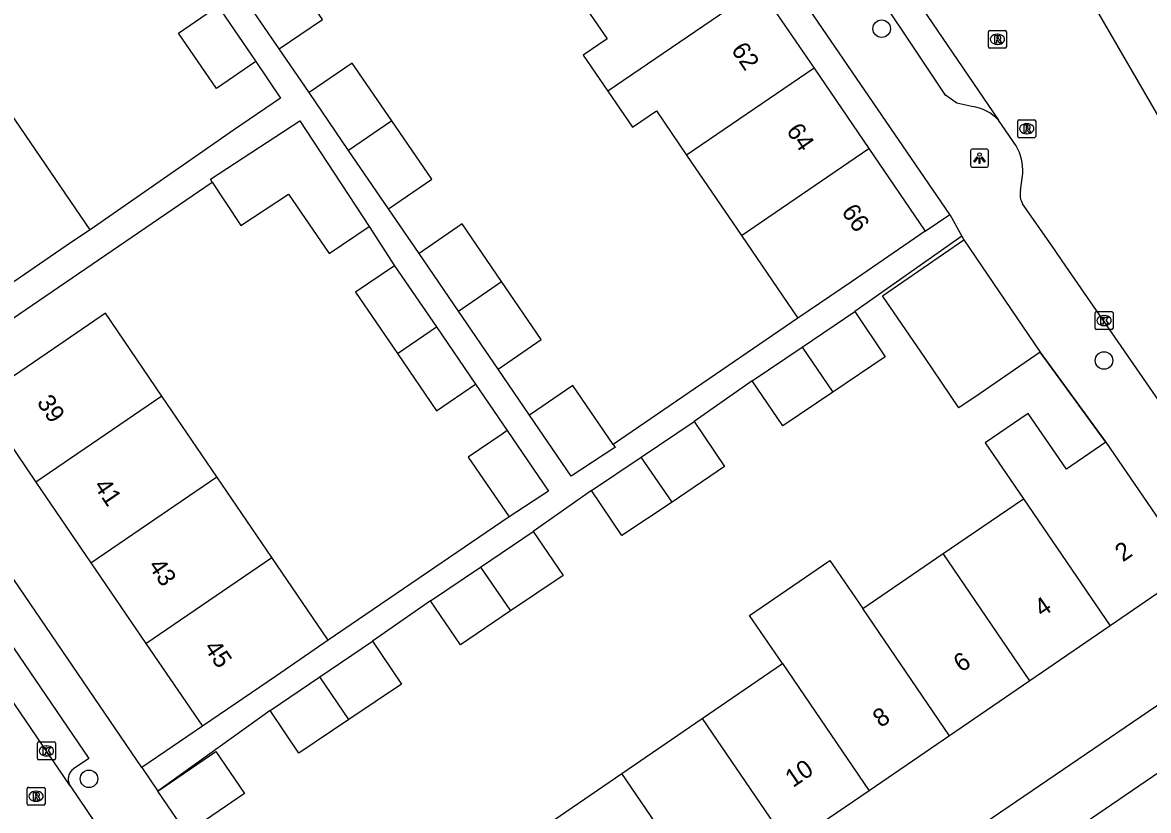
# Model space of a CAD drawing. Extents: x 157466 to 158888, y 383063 to 384677.
# Drawn here: x 158262.6 to 158325.5, y 383778.8 to 383822.7 of the extents above; entities that cross this region are included whole.
import ezdxf

# ---------------------------------------------------------------- set-up
doc = ezdxf.new("R2010")
doc.units = 0
for name, color, linetype in [('IMGEO_Boom', 7, 'Continuous'), ('IMGEO_Kolk', 7, 'Continuous'), ('IMGEO_Lichtpunt', 7, 'Continuous'), ('IMGEO_Muur', 7, 'Continuous'), ('IMGEO_Pand', 7, 'Continuous'), ('IMGEO_Pand_nummerreeks', 7, 'Continuous'), ('IMGEO_Rijbaan_lokaal_open', 7, 'Continuous'), ('IMGEO_Rioolput', 7, 'Continuous'), ('IMGEO_Voetpad_open', 7, 'Continuous')]:
    doc.layers.add(name, color=color, linetype=linetype)

msp = doc.modelspace()

# ---------------------------------------------------------------- linework, layer by layer
at = {"layer": 'IMGEO_Boom'}
for centre in [(158310.608, 383822.389), (158323.018, 383803.876), (158266.36, 383780.534)]:
    msp.add_circle(centre, 0.489, dxfattribs=at)
at = {"layer": 'IMGEO_Kolk'}
for p, q in [((158322.523, 383805.675), (158322.523, 383806.527)), ((158322.598, 383806.601), (158323.45, 383806.601)), ((158323.011, 383806.381), (158323.036, 383806.381)), ((158323.524, 383806.527), (158323.524, 383805.675)), ((158323.45, 383805.601), (158322.598, 383805.601)), ((158323.034, 383805.821), (158323.009, 383805.821)), ((158263.48, 383781.662), (158263.48, 383782.514)), ((158263.555, 383782.588), (158264.407, 383782.588)), ((158263.968, 383782.368), (158263.993, 383782.368)), ((158264.481, 383782.514), (158264.481, 383781.662)), ((158263.991, 383781.808), (158263.966, 383781.808)), ((158264.407, 383781.588), (158263.555, 383781.588))]:
    msp.add_line(p, q, dxfattribs=at)
for points in [[(158322.523, 383805.675), (158322.523, 383806.527)], [(158322.598, 383806.601), (158323.45, 383806.601)], [(158322.844, 383806.301), (158322.967, 383806.301), (158322.967, 383806.15), (158323.097, 383806.301), (158323.261, 383806.301), (158323.115, 383806.15), (158323.268, 383805.901), (158323.116, 383805.901), (158323.031, 383806.065), (158322.967, 383805.998), (158322.967, 383805.901), (158322.844, 383805.901), (158322.844, 383806.301)], [(158323.524, 383806.527), (158323.524, 383805.675)], [(158323.45, 383805.601), (158322.598, 383805.601)], [(158263.48, 383781.662), (158263.48, 383782.514)], [(158263.555, 383782.588), (158264.407, 383782.588)], [(158263.801, 383782.288), (158263.924, 383782.288), (158263.924, 383782.137), (158264.054, 383782.288), (158264.218, 383782.288), (158264.072, 383782.137), (158264.225, 383781.888), (158264.073, 383781.888), (158263.988, 383782.052), (158263.924, 383781.985), (158263.924, 383781.888), (158263.801, 383781.888), (158263.801, 383782.288)], [(158264.481, 383782.514), (158264.481, 383781.662)], [(158264.407, 383781.588), (158263.555, 383781.588)]]:
    msp.add_lwpolyline(points, dxfattribs=at)
for centre, start, end in [((158322.6, 383806.525), 91.55205, 178.44795), ((158322.6, 383806.525), 91.55205, 178.44795), ((158323.448, 383806.525), 1.55205, 88.44795), ((158323.448, 383806.525), 1.55205, 88.44795), ((158322.6, 383805.677), 181.55205, 268.44795), ((158322.6, 383805.677), 181.55205, 268.44795), ((158323.448, 383805.677), 271.55205, 358.44795), ((158323.448, 383805.677), 271.55205, 358.44795), ((158263.557, 383782.512), 91.55205, 178.44795), ((158263.557, 383782.512), 91.55205, 178.44795), ((158264.405, 383782.512), 1.55205, 88.44795), ((158264.405, 383782.512), 1.55205, 88.44795), ((158263.557, 383781.664), 181.55205, 268.44795), ((158263.557, 383781.664), 181.55205, 268.44795), ((158264.405, 383781.664), 271.55205, 358.44795), ((158264.405, 383781.664), 271.55205, 358.44795)]:
    msp.add_arc(centre, 0.0765, start, end, dxfattribs=at)
for centre, major_axis, ratio, start_param, end_param in [((158323.01, 383806.101), (-0.387, 0.002), 0.722429, 4.712389, 7.853982), ((158323.035, 383806.101), (-0.39, 0.002), 0.717154, 1.570796, 4.712389), ((158263.967, 383782.088), (-0.387, 0.002), 0.722429, 4.712389, 7.853982), ((158263.992, 383782.088), (-0.39, 0.002), 0.717154, 1.570796, 4.712389)]:
    msp.add_ellipse(centre, major_axis=major_axis, ratio=ratio, start_param=start_param, end_param=end_param, dxfattribs=at)
at = {"layer": 'IMGEO_Lichtpunt'}
for p, q in [((158315.572, 383815.572), (158315.572, 383814.765)), ((158315.572, 383815.572), (158315.572, 383814.765)), ((158316.474, 383815.667), (158315.666, 383815.667)), ((158316.474, 383815.667), (158315.666, 383815.667)), ((158316.568, 383814.765), (158316.568, 383815.572)), ((158316.568, 383814.765), (158316.568, 383815.572)), ((158315.666, 383814.671), (158316.474, 383814.671)), ((158315.666, 383814.671), (158316.474, 383814.671))]:
    msp.add_line(p, q, dxfattribs=at)
for points in [[(158315.946, 383815.236), (158315.985, 383815.208), (158315.797, 383814.946), (158315.759, 383814.973), (158315.946, 383815.236)], [(158316.048, 383815.188), (158316.095, 383815.188), (158316.095, 383814.866), (158316.048, 383814.866), (158316.048, 383815.188)], [(158316.158, 383815.208), (158316.196, 383815.235), (158316.383, 383814.973), (158316.344, 383814.945), (158316.158, 383815.208)]]:
    msp.add_lwpolyline(points, dxfattribs=at)
msp.add_circle((158316.071, 383815.37), 0.0994, dxfattribs=at)
for centre, start, end in [((158315.666, 383815.572), 90, 180), ((158315.666, 383815.572), 90, 180), ((158316.474, 383815.572), 0, 90), ((158316.474, 383815.572), 0, 90), ((158315.666, 383814.765), 180, 270), ((158315.666, 383814.765), 180, 270), ((158316.474, 383814.765), 270, 0), ((158316.474, 383814.765), 270, 360)]:
    msp.add_arc(centre, 0.0946, start, end, dxfattribs=at)
at = {"layer": 'IMGEO_Muur'}
msp.add_lwpolyline([(158323.13, 383799.314), (158319.462, 383804.339)], dxfattribs=at)
at = {"layer": 'IMGEO_Pand'}
for points in [[(158276.975, 383821.258), (158279.388, 383822.904), (158277.126, 383826.21)], [(158276.975, 383821.258), (158274.713, 383824.564)], [(158303.777, 383824.672), (158295.318, 383818.898)], [(158303.777, 383824.672), (158306.839, 383820.185)], [(158293.599, 383824.3), (158295.291, 383821.821), (158293.948, 383820.905), (158295.318, 383818.898)], [(158275.661, 383820.551), (158273.47, 383819.055), (158271.361, 383822.144), (158273.552, 383823.637)], [(158273.552, 383823.637), (158273.728, 383823.38), (158275.661, 383820.551)], [(158283.261, 383817.243), (158281.055, 383820.468), (158278.641, 383818.821)], [(158306.839, 383820.185), (158299.721, 383815.328)], [(158306.839, 383820.185), (158309.9, 383815.699)], [(158280.847, 383815.596), (158278.641, 383818.821)], [(158295.318, 383818.898), (158296.69, 383816.887), (158298.032, 383817.803), (158299.721, 383815.328)], [(158266.421, 383811.174), (158261.716, 383818.073)], [(158273.238, 383813.832), (158273.136, 383813.988), (158278.13, 383817.257), (158281.992, 383811.358)], [(158283.261, 383817.243), (158280.847, 383815.596)], [(158283.075, 383812.338), (158285.489, 383813.986), (158283.261, 383817.243)], [(158283.075, 383812.338), (158280.847, 383815.596)], [(158302.783, 383810.842), (158309.9, 383815.699)], [(158309.9, 383815.699), (158313.044, 383811.091)], [(158299.721, 383815.328), (158302.783, 383810.842)], [(158273.238, 383813.832), (158274.827, 383811.404), (158277.501, 383813.155), (158279.766, 383809.84), (158281.992, 383811.358)], [(158266.421, 383811.174), (158265.388, 383810.47), (158261.257, 383807.652)], [(158289.392, 383808.28), (158287.194, 383811.494), (158284.78, 383809.846)], [(158302.783, 383810.842), (158305.927, 383806.234)], [(158313.044, 383811.091), (158308.915, 383808.273), (158305.927, 383806.234)], [(158319.462, 383804.339), (158316.102, 383802.042), (158314.923, 383801.236), (158313.008, 383804.037), (158310.648, 383807.489), (158315.198, 383810.6)], [(158315.198, 383810.6), (158319.462, 383804.339)], [(158286.977, 383806.632), (158284.78, 383809.846)], [(158283.42, 383809.165), (158281.243, 383807.679), (158283.578, 383804.261)], [(158283.42, 383809.165), (158285.755, 383805.746)], [(158286.977, 383806.632), (158289.392, 383808.28)], [(158289.189, 383803.398), (158291.605, 383805.047), (158289.392, 383808.28)], [(158270.426, 383801.884), (158267.272, 383806.508), (158264.371, 383804.53), (158260.24, 383801.712), (158263.394, 383797.087)], [(158289.189, 383803.398), (158286.977, 383806.632)], [(158306.16, 383804.618), (158309.102, 383806.604)], [(158309.102, 383806.604), (158310.801, 383804.085), (158307.874, 383802.11)], [(158283.578, 383804.261), (158285.755, 383805.746)], [(158285.755, 383805.746), (158287.94, 383802.549)], [(158283.578, 383804.261), (158285.762, 383801.064), (158287.94, 383802.549)], [(158303.383, 383802.745), (158306.16, 383804.618)], [(158306.16, 383804.618), (158307.874, 383802.11)], [(158295.609, 383799.193), (158293.366, 383802.472), (158290.95, 383800.823)], [(158307.874, 383802.11), (158305.082, 383800.227), (158303.383, 383802.745)], [(158270.426, 383801.884), (158263.394, 383797.087)], [(158273.494, 383797.384), (158270.426, 383801.884)], [(158295.609, 383799.193), (158295.723, 383799.027), (158295.659, 383798.983), (158293.277, 383797.422), (158290.95, 383800.823)], [(158323.13, 383799.314), (158320.925, 383797.806), (158318.794, 383800.924), (158316.388, 383799.28), (158318.52, 383796.162)], [(158289.706, 383799.964), (158289.419, 383799.768), (158287.528, 383798.479), (158289.804, 383795.148)], [(158289.706, 383799.964), (158292.009, 383796.592), (158289.804, 383795.148)], [(158297.189, 383798.485), (158300.131, 383800.471)], [(158300.131, 383800.471), (158301.83, 383797.952), (158298.903, 383795.977)], [(158323.13, 383799.314), (158327.979, 383792.222)], [(158294.416, 383796.615), (158297.189, 383798.485)], [(158298.903, 383795.977), (158297.189, 383798.485)], [(158266.462, 383792.588), (158273.494, 383797.384)], [(158276.563, 383792.885), (158273.494, 383797.384)], [(158263.394, 383797.087), (158266.462, 383792.588)], [(158298.903, 383795.977), (158296.11, 383794.103), (158294.416, 383796.615)], [(158314.035, 383793.096), (158318.52, 383796.162)], [(158318.52, 383796.162), (158323.368, 383789.07)], [(158288.217, 383792.351), (158291.161, 383794.338)], [(158291.161, 383794.338), (158292.818, 383791.882), (158289.888, 383789.906)], [(158309.549, 383790.029), (158314.035, 383793.096)], [(158318.883, 383786.003), (158314.035, 383793.096)], [(158266.462, 383792.588), (158269.531, 383788.089)], [(158269.531, 383788.089), (158276.563, 383792.885)], [(158279.716, 383788.261), (158276.563, 383792.885)], [(158285.43, 383790.471), (158288.217, 383792.351)], [(158288.217, 383792.351), (158289.888, 383789.906)], [(158305.064, 383786.963), (158303.228, 383789.648), (158307.713, 383792.714), (158309.549, 383790.029)], [(158327.979, 383792.222), (158323.368, 383789.07)], [(158289.888, 383789.906), (158287.087, 383788.017), (158285.43, 383790.471)], [(158314.397, 383782.937), (158309.549, 383790.029)], [(158323.368, 383789.07), (158318.883, 383786.003)], [(158269.531, 383788.089), (158272.684, 383783.465)], [(158279.716, 383788.261), (158276.815, 383786.283), (158272.684, 383783.465)], [(158279.247, 383786.219), (158282.191, 383788.206)], [(158282.191, 383788.206), (158283.81, 383785.806), (158280.867, 383783.848)], [(158300.579, 383783.896), (158305.064, 383786.963)], [(158305.064, 383786.963), (158309.912, 383779.87)], [(158276.472, 383784.347), (158279.247, 383786.219)], [(158280.867, 383783.848), (158279.247, 383786.219)], [(158318.883, 383786.003), (158314.397, 383782.937)], [(158280.867, 383783.848), (158278.078, 383781.967), (158276.472, 383784.347)], [(158296.094, 383780.83), (158300.579, 383783.896)], [(158300.579, 383783.896), (158305.428, 383776.804)], [(158314.397, 383782.937), (158309.912, 383779.87)], [(158270.2, 383779.842), (158273.433, 383782.053), (158275.031, 383779.716), (158271.798, 383777.505)], [(158291.609, 383777.764), (158296.094, 383780.83)], [(158300.943, 383773.738), (158296.094, 383780.83)], [(158271.798, 383777.505), (158270.2, 383779.842)], [(158309.912, 383779.87), (158305.428, 383776.804)]]:
    msp.add_lwpolyline(points, dxfattribs=at)
at = {"layer": 'IMGEO_Rijbaan_lokaal_open'}
for points in [[(158266.381, 383891.427), (158290.926, 383855.558), (158294.957, 383849.841), (158317.136, 383817.278)], [(158320.491, 383827.07), (158327.485, 383815.039)], [(158318.12, 383815.849), (158317.136, 383817.278)], [(158318.359, 383813.367), (158318.48, 383814.317)], [(158331.81, 383793.339), (158322.603, 383806.659), (158320.882, 383809.145), (158320.086, 383810.314), (158318.47, 383812.617)], [(158265.297, 383780.146), (158255.069, 383795.151)], [(158265.297, 383780.146), (158265.304, 383780.135), (158267.164, 383777.394)]]:
    msp.add_lwpolyline(points, dxfattribs=at)
for centre, radius, start, end in [((158315.763, 383814.487), 2.723, 356.42583, 30.02185), ((158319.321, 383813.126), 0.992, 165.94685, 210.89047)]:
    msp.add_arc(centre, radius, start, end, dxfattribs=at)
at = {"layer": 'IMGEO_Rioolput'}
for p, q in [((158316.568, 383821.37), (158316.568, 383822.222)), ((158316.643, 383822.296), (158317.495, 383822.296)), ((158317.056, 383822.076), (158317.081, 383822.076)), ((158317.569, 383822.222), (158317.569, 383821.37)), ((158317.495, 383821.296), (158316.643, 383821.296)), ((158317.079, 383821.516), (158317.054, 383821.516)), ((158318.206, 383816.381), (158318.206, 383817.233)), ((158318.281, 383817.307), (158319.133, 383817.307)), ((158318.694, 383817.087), (158318.719, 383817.087)), ((158319.207, 383817.233), (158319.207, 383816.381)), ((158319.133, 383816.307), (158318.281, 383816.307)), ((158318.717, 383816.527), (158318.692, 383816.527)), ((158262.9, 383779.131), (158262.9, 383779.983)), ((158262.975, 383780.057), (158263.827, 383780.057)), ((158263.388, 383779.837), (158263.413, 383779.837)), ((158263.901, 383779.983), (158263.901, 383779.131)), ((158263.411, 383779.277), (158263.386, 383779.277)), ((158263.827, 383779.057), (158262.975, 383779.057))]:
    msp.add_line(p, q, dxfattribs=at)
for points in [[(158316.568, 383821.37), (158316.568, 383822.222)], [(158316.643, 383822.296), (158317.495, 383822.296)], [(158317.157, 383821.994), (158316.905, 383821.996), (158316.905, 383821.596)], [(158317.083, 383821.915), (158317.029, 383821.915), (158317.029, 383821.834)], [(158317.569, 383822.222), (158317.569, 383821.37)], [(158317.495, 383821.296), (158316.643, 383821.296)], [(158316.905, 383821.596), (158317.029, 383821.596), (158317.029, 383821.758), (158317.04, 383821.758)], [(158317.029, 383821.834), (158317.081, 383821.834)], [(158317.087, 383821.729), (158317.158, 383821.596), (158317.298, 383821.596), (158317.233, 383821.722)], [(158318.206, 383816.381), (158318.206, 383817.233)], [(158318.281, 383817.307), (158319.133, 383817.307)], [(158318.795, 383817.005), (158318.543, 383817.007), (158318.543, 383816.607)], [(158318.721, 383816.926), (158318.667, 383816.926), (158318.667, 383816.845)], [(158318.667, 383816.845), (158318.719, 383816.845)], [(158319.207, 383817.233), (158319.207, 383816.381)], [(158319.133, 383816.307), (158318.281, 383816.307)], [(158318.543, 383816.607), (158318.667, 383816.607), (158318.667, 383816.769), (158318.678, 383816.769)], [(158318.725, 383816.74), (158318.796, 383816.607), (158318.936, 383816.607), (158318.871, 383816.733)], [(158262.9, 383779.131), (158262.9, 383779.983)], [(158262.975, 383780.057), (158263.827, 383780.057)], [(158263.489, 383779.755), (158263.237, 383779.757), (158263.237, 383779.357)], [(158263.901, 383779.983), (158263.901, 383779.131)], [(158263.237, 383779.357), (158263.361, 383779.357), (158263.361, 383779.519), (158263.372, 383779.519)], [(158263.415, 383779.676), (158263.361, 383779.676), (158263.361, 383779.595)], [(158263.361, 383779.595), (158263.413, 383779.595)], [(158263.419, 383779.49), (158263.49, 383779.357), (158263.63, 383779.357), (158263.565, 383779.483)], [(158263.827, 383779.057), (158262.975, 383779.057)]]:
    msp.add_lwpolyline(points, dxfattribs=at)
for centre, radius, start, end in [((158316.645, 383822.22), 0.0765, 91.55205, 178.44795), ((158316.645, 383822.22), 0.0765, 91.55205, 178.44795), ((158317.089, 383821.819), 0.0964, 77.00612, 93.18647), ((158317.103, 383821.876), 0.0378, 276.66336, 79.67722), ((158317.156, 383821.884), 0.109, 350.36119, 89.41601), ((158317.154, 383821.884), 0.112, 277.58423, 350.98172), ((158317.493, 383822.22), 0.0765, 1.55205, 88.44795), ((158317.493, 383822.22), 0.0765, 1.55205, 88.44795), ((158316.645, 383821.372), 0.0765, 181.55205, 268.44795), ((158316.645, 383821.372), 0.0765, 181.55205, 268.44795), ((158317.039, 383821.705), 0.0533, 26.02933, 88.69889), ((158317.065, 383822.023), 0.19, 274.7715, 282.96867), ((158317.138, 383821.669), 0.108, 29.51342, 73.79051), ((158317.493, 383821.372), 0.0765, 271.55205, 358.44795), ((158317.493, 383821.372), 0.0765, 271.55205, 358.44795), ((158318.283, 383817.231), 0.0765, 91.55205, 178.44795), ((158318.283, 383817.231), 0.0765, 91.55205, 178.44795), ((158318.703, 383817.034), 0.19, 274.7715, 282.96867), ((158318.727, 383816.83), 0.0964, 77.00612, 93.18647), ((158318.741, 383816.887), 0.0378, 276.66336, 79.67722), ((158318.794, 383816.895), 0.109, 350.36119, 89.41601), ((158318.792, 383816.895), 0.112, 277.58423, 350.98172), ((158319.131, 383817.231), 0.0765, 1.55205, 88.44795), ((158319.131, 383817.231), 0.0765, 1.55205, 88.44795), ((158318.283, 383816.383), 0.0765, 181.55205, 268.44795), ((158318.283, 383816.383), 0.0765, 181.55205, 268.44795), ((158318.677, 383816.716), 0.0533, 26.02933, 88.69889), ((158318.776, 383816.68), 0.108, 29.51342, 73.79051), ((158319.131, 383816.383), 0.0765, 271.55205, 358.44795), ((158319.131, 383816.383), 0.0765, 271.55205, 358.44795), ((158262.977, 383779.981), 0.0765, 91.55205, 178.44795), ((158262.977, 383779.981), 0.0765, 91.55205, 178.44795), ((158263.488, 383779.645), 0.109, 350.36119, 89.41601), ((158263.825, 383779.981), 0.0765, 1.55205, 88.44795), ((158263.825, 383779.981), 0.0765, 1.55205, 88.44795), ((158262.977, 383779.133), 0.0765, 181.55205, 268.44795), ((158262.977, 383779.133), 0.0765, 181.55205, 268.44795), ((158263.371, 383779.466), 0.0533, 26.02933, 88.69889), ((158263.397, 383779.784), 0.19, 274.7715, 282.96867), ((158263.421, 383779.58), 0.0964, 77.00612, 93.18647), ((158263.435, 383779.637), 0.0378, 276.66336, 79.67722), ((158263.486, 383779.645), 0.112, 277.58423, 350.98172), ((158263.47, 383779.43), 0.108, 29.51342, 73.79051), ((158263.825, 383779.133), 0.0765, 271.55205, 358.44795), ((158263.825, 383779.133), 0.0765, 271.55205, 358.44795)]:
    msp.add_arc(centre, radius, start, end, dxfattribs=at)
for centre, major_axis, ratio, start_param, end_param in [((158317.055, 383821.796), (-0.387, 0.002), 0.722429, 4.712389, 7.853982), ((158317.08, 383821.796), (-0.39, 0.002), 0.717154, 1.570796, 4.712389), ((158318.693, 383816.807), (-0.387, 0.002), 0.722429, 4.712389, 7.853982), ((158318.718, 383816.807), (-0.39, 0.002), 0.717154, 1.570796, 4.712389), ((158263.387, 383779.557), (-0.387, 0.002), 0.722429, 4.712389, 7.853982), ((158263.412, 383779.557), (-0.39, 0.002), 0.717154, 1.570796, 4.712389)]:
    msp.add_ellipse(centre, major_axis=major_axis, ratio=ratio, start_param=start_param, end_param=end_param, dxfattribs=at)
at = {"layer": 'IMGEO_Voetpad_open'}
for points in [[(158315.648, 383818.052), (158314.799, 383818.227), (158314.179, 383818.673), (158308.868, 383826.633), (158286.012, 383859.903), (158283.979, 383862.899), (158256.861, 383902.472)], [(158314.406, 383812.02), (158283.568, 383857.085)], [(158278.641, 383818.821), (158276.975, 383821.258)], [(158275.661, 383820.551), (158277.048, 383818.521), (158274.432, 383816.734), (158266.421, 383811.174)], [(158255.342, 383801.626), (158273.238, 383813.832)], [(158284.78, 383809.846), (158283.075, 383812.338)], [(158313.044, 383811.091), (158314.406, 383812.02)], [(158314.406, 383812.02), (158315.08, 383810.811)], [(158281.992, 383811.358), (158283.42, 383809.165)], [(158315.08, 383810.811), (158309.102, 383806.604)], [(158315.08, 383810.811), (158315.198, 383810.6)], [(158305.927, 383806.234), (158295.609, 383799.193)], [(158319.462, 383804.339), (158323.13, 383799.314)], [(158290.95, 383800.823), (158289.189, 383803.398)], [(158287.94, 383802.549), (158289.706, 383799.964)], [(158303.383, 383802.745), (158300.131, 383800.471)], [(158269.302, 383781.158), (158255.342, 383801.626)], [(158294.416, 383796.615), (158291.161, 383794.338)], [(158257.041, 383795.301), (158266.338, 383781.661), (158265.5, 383781.089), (158265.45, 383781.051), (158265.403, 383781.01), (158265.361, 383780.964), (158265.322, 383780.914), (158265.289, 383780.861), (158265.26, 383780.806), (158265.236, 383780.748), (158265.217, 383780.688), (158265.204, 383780.627), (158265.197, 383780.565), (158265.195, 383780.502), (158265.198, 383780.44), (158265.207, 383780.378), (158265.222, 383780.317), (158265.242, 383780.258), (158265.267, 383780.2), (158265.297, 383780.146)], [(158289.804, 383795.148), (158279.716, 383788.261)], [(158285.43, 383790.471), (158282.191, 383788.206)], [(158285.703, 383757.214), (158328.509, 383786.356), (158330.843, 383787.992)], [(158276.472, 383784.347), (158270.2, 383779.842)], [(158272.684, 383783.465), (158269.302, 383781.158)], [(158269.302, 383781.158), (158270.2, 383779.842)], [(158291.616, 383757.372), (158326.484, 383781.177)]]:
    msp.add_lwpolyline(points, dxfattribs=at)
msp.add_arc((158315.309, 383815.583), 2.492, 42.85136, 82.18523, dxfattribs=at)

# ---------------------------------------------------------------- texts
at = {"layer": 'IMGEO_Pand_nummerreeks'}
for s, rotation, p in [('62', 304.30792, (158302.173, 383821.203)), ('64', 304.30792, (158305.252, 383816.69)), ('66', 304.30792, (158308.33, 383812.18)), ('39', 304.29301, (158263.411, 383801.533)), ('41', 304.29301, (158266.586, 383796.878)), ('2', 34.36028, (158324.072, 383792.604)), ('43', 304.29301, (158269.633, 383792.41)), ('4', 34.35943, (158319.565, 383789.522)), ('45', 304.29301, (158272.744, 383787.848)), ('6', 34.35943, (158315.055, 383786.439)), ('8', 34.36028, (158310.549, 383783.358)), ('10', 34.35943, (158305.659, 383780.015))]:
    msp.add_text(s, height=1, rotation=rotation, dxfattribs=at).set_placement(p)

doc.saveas('drawing.dxf')
